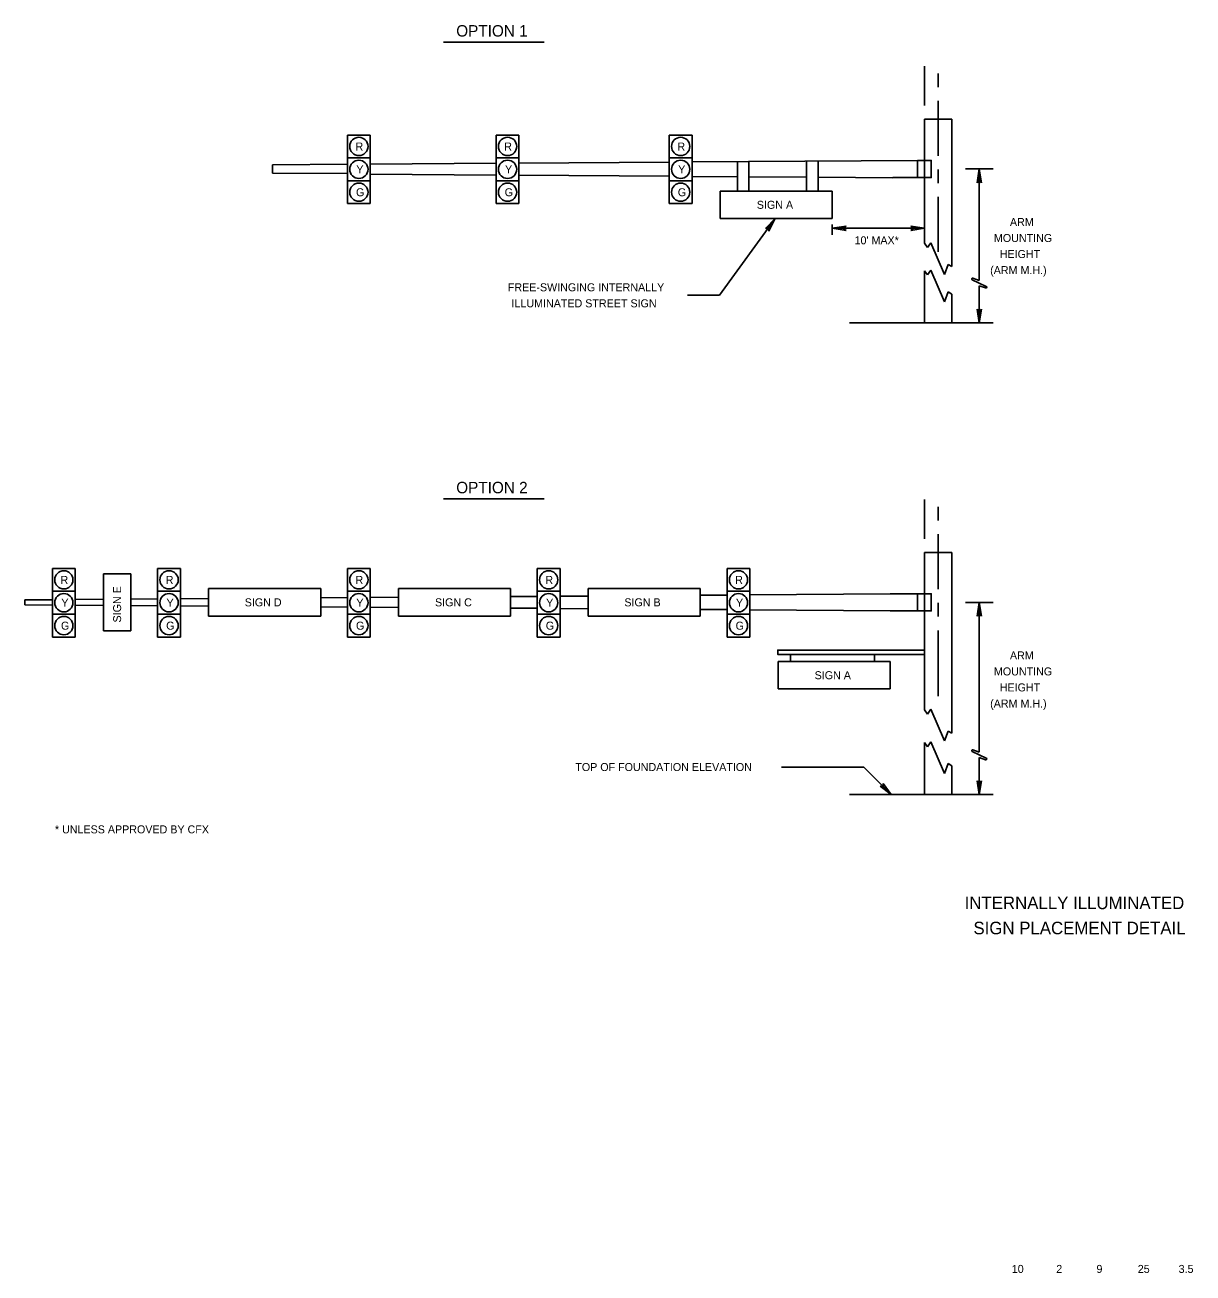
# Model space of a CAD drawing. Extents: x 2146427 to 2147986, y 2147023 to 2147568.
# Drawn here: x 2147047 to 2147558, y 2147023 to 2147568 of the extents above; entities that cross this region are included whole.
import ezdxf

# ---------------------------------------------------------------- set-up
doc = ezdxf.new("R2010")
doc.units = 0
doc.layers.add('50', color=7, linetype='Continuous')
doc.layers.add('TextMisc', color=7, linetype='Continuous')

msp = doc.modelspace()

# ---------------------------------------------------------------- linework, layer by layer
at = {"layer": '50'}
for p, q in [((2147230.35, 2147560.7), (2147274.35, 2147560.7)), ((2147440.6, 2147533.04), (2147440.6, 2147550.29)), ((2147446.6, 2147541.04), (2147446.6, 2147547.04)), ((2147446.6, 2147535.04), (2147446.6, 2147511.04)), ((2147440.6, 2147527.04), (2147452.6, 2147527.04)), ((2147440.6, 2147527.04), (2147440.6, 2147472.8)), ((2147452.6, 2147527.04), (2147452.6, 2147462.6)), ((2147198.3, 2147520.13), (2147188.3, 2147520.13)), ((2147188.3, 2147520.13), (2147188.3, 2147490.13)), ((2147198.3, 2147520.13), (2147198.3, 2147490.13)), ((2147263.32, 2147520.13), (2147253.32, 2147520.13)), ((2147253.32, 2147520.13), (2147253.32, 2147490.13)), ((2147263.32, 2147520.13), (2147263.32, 2147490.13)), ((2147339.02, 2147520.13), (2147329.02, 2147520.13)), ((2147329.02, 2147520.13), (2147329.02, 2147490.13)), ((2147339.02, 2147520.13), (2147339.02, 2147490.13)), ((2147198.3, 2147510.13), (2147188.3, 2147510.13)), ((2147263.32, 2147510.13), (2147253.32, 2147510.13)), ((2147329.02, 2147508.3), (2147263.32, 2147507.85)), ((2147339.02, 2147510.13), (2147329.02, 2147510.13)), ((2147437.6, 2147509.04), (2147339.02, 2147508.37)), ((2147358.83, 2147508.68), (2147358.83, 2147495.61)), ((2147363.83, 2147508.68), (2147363.83, 2147495.61)), ((2147389.08, 2147508.88), (2147389.08, 2147495.61)), ((2147394.08, 2147508.88), (2147394.08, 2147495.57)), ((2147188.3, 2147507.34), (2147155.52, 2147507.12)), ((2147155.52, 2147503.47), (2147155.52, 2147507.12)), ((2147188.3, 2147503.24), (2147155.52, 2147503.47)), ((2147253.32, 2147507.78), (2147198.3, 2147507.41)), ((2147253.32, 2147502.63), (2147198.3, 2147503)), ((2147446.6, 2147499.04), (2147446.6, 2147505.04)), ((2147458.6, 2147505.29), (2147470.6, 2147505.29)), ((2147464.6, 2147505.29), (2147463.7, 2147499.29)), ((2147465.5, 2147499.29), (2147464.6, 2147505.29)), ((2147464.6, 2147505.29), (2147464.6, 2147456.53)), ((2147198.3, 2147500.13), (2147188.3, 2147500.13)), ((2147263.32, 2147500.13), (2147253.32, 2147500.13)), ((2147329.02, 2147502.11), (2147263.32, 2147502.56)), ((2147339.02, 2147500.13), (2147329.02, 2147500.13)), ((2147358.83, 2147501.91), (2147339.02, 2147502.04)), ((2147389.08, 2147501.7), (2147363.83, 2147501.87)), ((2147426.78, 2147501.44), (2147394.08, 2147501.67)), ((2147437.6, 2147501.54), (2147426.85, 2147501.62)), ((2147463.7, 2147499.29), (2147464.6, 2147500.49)), ((2147464.6, 2147500.49), (2147465.5, 2147499.29)), ((2147351.33, 2147495.61), (2147400.33, 2147495.61)), ((2147351.33, 2147495.61), (2147351.33, 2147483.61)), ((2147400.33, 2147495.61), (2147400.33, 2147483.61)), ((2147446.6, 2147493.04), (2147446.6, 2147469.04)), ((2147188.3, 2147490.13), (2147198.3, 2147490.13)), ((2147253.32, 2147490.13), (2147263.32, 2147490.13)), ((2147329.02, 2147490.13), (2147339.02, 2147490.13)), ((2147375.38, 2147483.61), (2147351.05, 2147450.04)), ((2147351.33, 2147483.61), (2147400.33, 2147483.61)), ((2147375.27, 2147483.59), (2147371.1, 2147479.19)), ((2147372.57, 2147478.15), (2147375.27, 2147483.59)), ((2147400.33, 2147481.04), (2147400.33, 2147476.52)), ((2147371.1, 2147479.19), (2147372.52, 2147479.65)), ((2147372.52, 2147479.65), (2147372.57, 2147478.15)), ((2147400.33, 2147479.34), (2147406.33, 2147480.24)), ((2147400.33, 2147479.34), (2147440.6, 2147479.34)), ((2147406.33, 2147478.44), (2147400.33, 2147479.34)), ((2147406.33, 2147480.24), (2147405.13, 2147479.34)), ((2147405.13, 2147479.34), (2147406.33, 2147478.44)), ((2147440.6, 2147479.34), (2147434.6, 2147480.24)), ((2147434.6, 2147480.24), (2147435.8, 2147479.34)), ((2147435.8, 2147479.34), (2147434.6, 2147478.44)), ((2147434.6, 2147478.44), (2147440.6, 2147479.34)), ((2147440.6, 2147472.8), (2147442, 2147470.93)), ((2147442, 2147470.93), (2147443.41, 2147473.05)), ((2147443.41, 2147473.05), (2147449.31, 2147459.21)), ((2147440.6, 2147460.8), (2147440.6, 2147438.04)), ((2147440.6, 2147460.8), (2147442, 2147458.93)), ((2147442, 2147458.93), (2147443.41, 2147461.05)), ((2147443.41, 2147461.05), (2147449.31, 2147447.21)), ((2147449.31, 2147459.21), (2147451.02, 2147463.54)), ((2147451.02, 2147463.54), (2147452.6, 2147462.6)), ((2147461.54, 2147456.84), (2147467.64, 2147453.89)), ((2147461.84, 2147457.54), (2147464.59, 2147456.54)), ((2147464.59, 2147454.24), (2147467.34, 2147453.24)), ((2147464.6, 2147454.23), (2147464.6, 2147438.04)), ((2147351.05, 2147450.04), (2147337.01, 2147450.04)), ((2147449.31, 2147447.21), (2147451.02, 2147451.54)), ((2147451.02, 2147451.54), (2147452.6, 2147450.6)), ((2147452.6, 2147450.6), (2147452.6, 2147438.04)), ((2147464.6, 2147442.84), (2147463.7, 2147444.04)), ((2147463.7, 2147444.04), (2147464.6, 2147438.04)), ((2147464.6, 2147438.04), (2147465.5, 2147444.04)), ((2147465.5, 2147444.04), (2147464.6, 2147442.84)), ((2147407.85, 2147438.04), (2147470.6, 2147438.04)), ((2147230.35, 2147361.01), (2147274.35, 2147361.01)), ((2147440.6, 2147343.54), (2147440.6, 2147360.79)), ((2147446.6, 2147351.54), (2147446.6, 2147357.54)), ((2147446.6, 2147345.54), (2147446.6, 2147321.54)), ((2147440.6, 2147337.54), (2147452.6, 2147337.54)), ((2147440.6, 2147337.54), (2147440.6, 2147268.76)), ((2147452.6, 2147337.54), (2147452.6, 2147258.56)), ((2147069.3, 2147330.63), (2147059.3, 2147330.63)), ((2147059.3, 2147330.63), (2147059.3, 2147300.63)), ((2147069.3, 2147330.63), (2147069.3, 2147300.63)), ((2147081.6, 2147328.29), (2147081.6, 2147303.29)), ((2147081.6, 2147328.29), (2147093.6, 2147328.29)), ((2147093.6, 2147328.29), (2147093.6, 2147303.29)), ((2147115.3, 2147330.63), (2147105.3, 2147330.63)), ((2147105.3, 2147330.63), (2147105.3, 2147300.63)), ((2147115.3, 2147330.63), (2147115.3, 2147300.63)), ((2147198.3, 2147330.63), (2147188.3, 2147330.63)), ((2147188.3, 2147330.63), (2147188.3, 2147300.63)), ((2147198.3, 2147330.63), (2147198.3, 2147300.63)), ((2147281.3, 2147330.63), (2147271.3, 2147330.63)), ((2147271.3, 2147330.63), (2147271.3, 2147300.63)), ((2147281.3, 2147330.63), (2147281.3, 2147300.63)), ((2147364.3, 2147330.63), (2147354.3, 2147330.63)), ((2147354.3, 2147330.63), (2147354.3, 2147300.63)), ((2147364.3, 2147330.63), (2147364.3, 2147300.63)), ((2147069.3, 2147320.63), (2147059.3, 2147320.63)), ((2147105.3, 2147317.27), (2147093.6, 2147317.19)), ((2147115.3, 2147320.63), (2147105.3, 2147320.63)), ((2147127.6, 2147317.42), (2147115.3, 2147317.34)), ((2147127.6, 2147321.79), (2147176.6, 2147321.79)), ((2147127.6, 2147321.79), (2147127.6, 2147309.79)), ((2147176.6, 2147321.79), (2147176.6, 2147309.79)), ((2147188.3, 2147317.84), (2147176.6, 2147317.76)), ((2147198.3, 2147320.63), (2147188.3, 2147320.63)), ((2147210.6, 2147317.99), (2147198.3, 2147317.91)), ((2147210.6, 2147321.79), (2147259.6, 2147321.79)), ((2147210.6, 2147321.79), (2147210.6, 2147309.79)), ((2147259.6, 2147321.79), (2147259.6, 2147309.79)), ((2147271.3, 2147318.41), (2147259.6, 2147318.33)), ((2147281.3, 2147320.63), (2147271.3, 2147320.63)), ((2147293.6, 2147318.56), (2147281.3, 2147318.47)), ((2147293.6, 2147321.79), (2147342.6, 2147321.79)), ((2147293.6, 2147321.79), (2147293.6, 2147309.79)), ((2147342.6, 2147321.79), (2147342.6, 2147309.79)), ((2147354.3, 2147318.97), (2147342.6, 2147318.89)), ((2147364.3, 2147320.63), (2147354.3, 2147320.63)), ((2147425.6, 2147319.46), (2147364.3, 2147319.04)), ((2147437.6, 2147319.54), (2147425.6, 2147319.46)), ((2147059.3, 2147316.96), (2147047.3, 2147316.88)), ((2147047.3, 2147314.71), (2147047.3, 2147316.88)), ((2147059.3, 2147314.62), (2147047.3, 2147314.71)), ((2147081.6, 2147317.11), (2147069.3, 2147317.03)), ((2147081.6, 2147314.47), (2147069.3, 2147314.56)), ((2147105.3, 2147314.31), (2147093.6, 2147314.39)), ((2147127.6, 2147314.16), (2147115.3, 2147314.24)), ((2147188.3, 2147313.74), (2147176.6, 2147313.82)), ((2147210.6, 2147313.59), (2147198.3, 2147313.68)), ((2147271.3, 2147313.18), (2147259.6, 2147313.26)), ((2147293.6, 2147313.02), (2147281.3, 2147313.11)), ((2147354.3, 2147312.61), (2147342.6, 2147312.69)), ((2147425.6, 2147312.12), (2147364.3, 2147312.54)), ((2147437.6, 2147312.04), (2147425.6, 2147312.12)), ((2147446.6, 2147309.54), (2147446.6, 2147315.54)), ((2147458.6, 2147315.79), (2147470.6, 2147315.79)), ((2147464.6, 2147315.79), (2147463.7, 2147309.79)), ((2147465.5, 2147309.79), (2147464.6, 2147315.79)), ((2147464.6, 2147315.79), (2147464.6, 2147250.28)), ((2147069.3, 2147310.63), (2147059.3, 2147310.63)), ((2147115.3, 2147310.63), (2147105.3, 2147310.63)), ((2147127.6, 2147309.79), (2147176.6, 2147309.79)), ((2147198.3, 2147310.63), (2147188.3, 2147310.63)), ((2147210.6, 2147309.79), (2147259.6, 2147309.79)), ((2147281.3, 2147310.63), (2147271.3, 2147310.63)), ((2147293.6, 2147309.79), (2147342.6, 2147309.79)), ((2147364.3, 2147310.63), (2147354.3, 2147310.63)), ((2147463.7, 2147309.79), (2147464.6, 2147310.99)), ((2147464.6, 2147310.99), (2147465.5, 2147309.79)), ((2147081.6, 2147303.29), (2147093.6, 2147303.29)), ((2147446.6, 2147303.54), (2147446.6, 2147274.76)), ((2147059.3, 2147300.63), (2147069.3, 2147300.63)), ((2147105.3, 2147300.63), (2147115.3, 2147300.63)), ((2147188.3, 2147300.63), (2147198.3, 2147300.63)), ((2147271.3, 2147300.63), (2147281.3, 2147300.63)), ((2147354.3, 2147300.63), (2147364.3, 2147300.63)), ((2147376.6, 2147289.92), (2147425.6, 2147289.92)), ((2147376.6, 2147289.92), (2147376.6, 2147277.92)), ((2147382.01, 2147293.05), (2147382.01, 2147289.92)), ((2147418.78, 2147293.05), (2147418.78, 2147289.92)), ((2147425.6, 2147289.92), (2147425.6, 2147277.92)), ((2147376.6, 2147277.92), (2147425.6, 2147277.92)), ((2147440.6, 2147268.76), (2147442, 2147266.9)), ((2147442, 2147266.9), (2147443.41, 2147269.01)), ((2147443.41, 2147269.01), (2147449.31, 2147255.17)), ((2147449.31, 2147255.17), (2147451.02, 2147259.51)), ((2147451.02, 2147259.51), (2147452.6, 2147258.56)), ((2147440.6, 2147254.53), (2147440.6, 2147231.78)), ((2147440.6, 2147254.53), (2147442, 2147252.67)), ((2147442, 2147252.67), (2147443.41, 2147254.79)), ((2147443.41, 2147254.79), (2147449.31, 2147240.94)), ((2147461.54, 2147250.58), (2147467.64, 2147247.63)), ((2147461.84, 2147251.28), (2147464.59, 2147250.28)), ((2147464.59, 2147247.98), (2147467.34, 2147246.98)), ((2147464.6, 2147247.97), (2147464.6, 2147231.78)), ((2147414.1, 2147243.78), (2147378.1, 2147243.78)), ((2147426.1, 2147231.78), (2147414.1, 2147243.78)), ((2147449.31, 2147240.94), (2147451.02, 2147245.28)), ((2147451.02, 2147245.28), (2147452.6, 2147244.33)), ((2147452.6, 2147244.33), (2147452.6, 2147231.78)), ((2147422.71, 2147235.17), (2147421.22, 2147235.38)), ((2147421.22, 2147235.38), (2147426.1, 2147231.78)), ((2147426.1, 2147231.78), (2147422.5, 2147236.65)), ((2147422.5, 2147236.65), (2147422.71, 2147235.17)), ((2147464.6, 2147236.58), (2147463.7, 2147237.78)), ((2147463.7, 2147237.78), (2147464.6, 2147231.78)), ((2147464.6, 2147231.78), (2147465.5, 2147237.78)), ((2147465.5, 2147237.78), (2147464.6, 2147236.58)), ((2147407.85, 2147231.78), (2147470.6, 2147231.78))]:
    msp.add_line(p, q, dxfattribs=at)
for points in [[(2147437.6, 2147509.04), (2147437.6, 2147501.54), (2147443.6, 2147501.54), (2147443.6, 2147509.04)], [(2147437.6, 2147319.54), (2147437.6, 2147312.04), (2147443.6, 2147312.04), (2147443.6, 2147319.54)], [(2147440.6, 2147294.89), (2147376.47, 2147294.89), (2147376.47, 2147293.05), (2147440.6, 2147293.05)]]:
    msp.add_lwpolyline(points, close=True, dxfattribs=at)
for centre in [(2147193.3, 2147515.13), (2147258.32, 2147515.13), (2147334.02, 2147515.13), (2147193.3, 2147505.13), (2147258.32, 2147505.13), (2147334.02, 2147505.13), (2147193.3, 2147495.13), (2147258.32, 2147495.13), (2147334.02, 2147495.13), (2147064.3, 2147325.63), (2147110.3, 2147325.63), (2147193.3, 2147325.63), (2147276.3, 2147325.63), (2147359.3, 2147325.63), (2147064.3, 2147315.63), (2147110.3, 2147315.63), (2147193.3, 2147315.63), (2147276.3, 2147315.63), (2147359.3, 2147315.63), (2147064.3, 2147305.63), (2147110.3, 2147305.63), (2147193.3, 2147305.63), (2147276.3, 2147305.63), (2147359.3, 2147305.63)]:
    msp.add_circle(centre, 4, dxfattribs=at)
for centre, start, end in [((2147461.67, 2147457.2), 68.5892, 245.0075), ((2147467.5, 2147453.58), 248.5892, 65.0075), ((2147461.67, 2147250.94), 68.5892, 245.0075), ((2147467.5, 2147247.31), 248.5892, 65.0075)]:
    msp.add_arc(centre, 0.37, start, end, dxfattribs=at)

# ---------------------------------------------------------------- texts
for s, height, p in [('OPTION 1', 5, (2147235.88, 2147563.17)), ('R', 3.5, (2147191.84, 2147513.34)), ('R', 3.5, (2147256.87, 2147513.34)), ('R', 3.5, (2147332.57, 2147513.34)), ('Y', 3.5, (2147192.19, 2147503.34)), ('Y', 3.5, (2147257.22, 2147503.34)), ('Y', 3.5, (2147332.92, 2147503.34)), ('G', 3.5, (2147192.04, 2147493.34)), ('G', 3.5, (2147257.07, 2147493.34)), ('G', 3.5, (2147332.77, 2147493.34)), ('SIGN A', 3.5, (2147367.32, 2147487.86)), ('ARM', 3.5, (2147477.99, 2147480.34)), ("10' MAX*", 3.5, (2147410.05, 2147472.34)), ('MOUNTING', 3.5, (2147470.99, 2147473.34)), ('HEIGHT', 3.5, (2147473.54, 2147466.34)), ('(ARM M.H.)', 3.5, (2147469.34, 2147459.29)), ('FREE-SWINGING INTERNALLY', 3.5001, (2147258.44, 2147451.79)), ('ILLUMINATED STREET SIGN', 3.5001, (2147260.04, 2147444.79)), ('OPTION 2', 5, (2147235.88, 2147363.48)), ('R', 3.5, (2147062.84, 2147323.84)), ('R', 3.5, (2147108.84, 2147323.84)), ('R', 3.5, (2147191.84, 2147323.84)), ('R', 3.5, (2147274.84, 2147323.84)), ('R', 3.5, (2147357.84, 2147323.84)), ('Y', 3.5, (2147063.19, 2147313.84)), ('Y', 3.5, (2147109.19, 2147313.84)), ('SIGN D', 3.5, (2147143.39, 2147314.04)), ('Y', 3.5, (2147192.19, 2147313.84)), ('SIGN C', 3.5, (2147226.59, 2147314.04)), ('Y', 3.5, (2147275.19, 2147313.84)), ('SIGN B', 3.5, (2147309.39, 2147314.04)), ('Y', 3.5, (2147358.19, 2147313.84)), ('G', 3.5, (2147063.04, 2147303.84)), ('G', 3.5, (2147109.04, 2147303.84)), ('G', 3.5, (2147192.04, 2147303.84)), ('G', 3.5, (2147275.04, 2147303.84)), ('G', 3.5, (2147358.04, 2147303.84)), ('ARM', 3.5, (2147477.99, 2147290.84)), ('SIGN A', 3.5, (2147392.59, 2147282.17)), ('MOUNTING', 3.5, (2147470.99, 2147283.84)), ('HEIGHT', 3.5, (2147473.54, 2147276.84)), ('(ARM M.H.)', 3.5, (2147469.34, 2147269.79)), ('TOP OF FOUNDATION ELEVATION', 3.5001, (2147287.94, 2147242.03)), ('* UNLESS APPROVED BY CFX', 3.5001, (2147060.39, 2147214.77)), ('10', 3.5, (2147478.8, 2147022.58)), ('2', 3.5, (2147498.24, 2147022.58)), ('9', 3.5, (2147515.83, 2147022.58)), ('25', 3.5, (2147533.89, 2147022.58)), ('3.5', 3.5, (2147551.75, 2147022.58))]:
    msp.add_text(s, height=height, dxfattribs=at).set_placement(p)
msp.add_text('SIGN E', height=3.5, rotation=90, dxfattribs=at).set_placement((2147089.34, 2147306.99))
at = {"layer": 'TextMisc'}
for s, p in [('INTERNALLY ILLUMINATED', (2147458.18, 2147181.64)), ('SIGN PLACEMENT DETAIL', (2147462.03, 2147170.64))]:
    msp.add_text(s, height=5.5, dxfattribs=at).set_placement(p)

doc.saveas('drawing.dxf')
